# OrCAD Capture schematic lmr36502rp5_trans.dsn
size B; title: LMR36502RP5 Steady State Schematic; rev: A; note: <Doc>
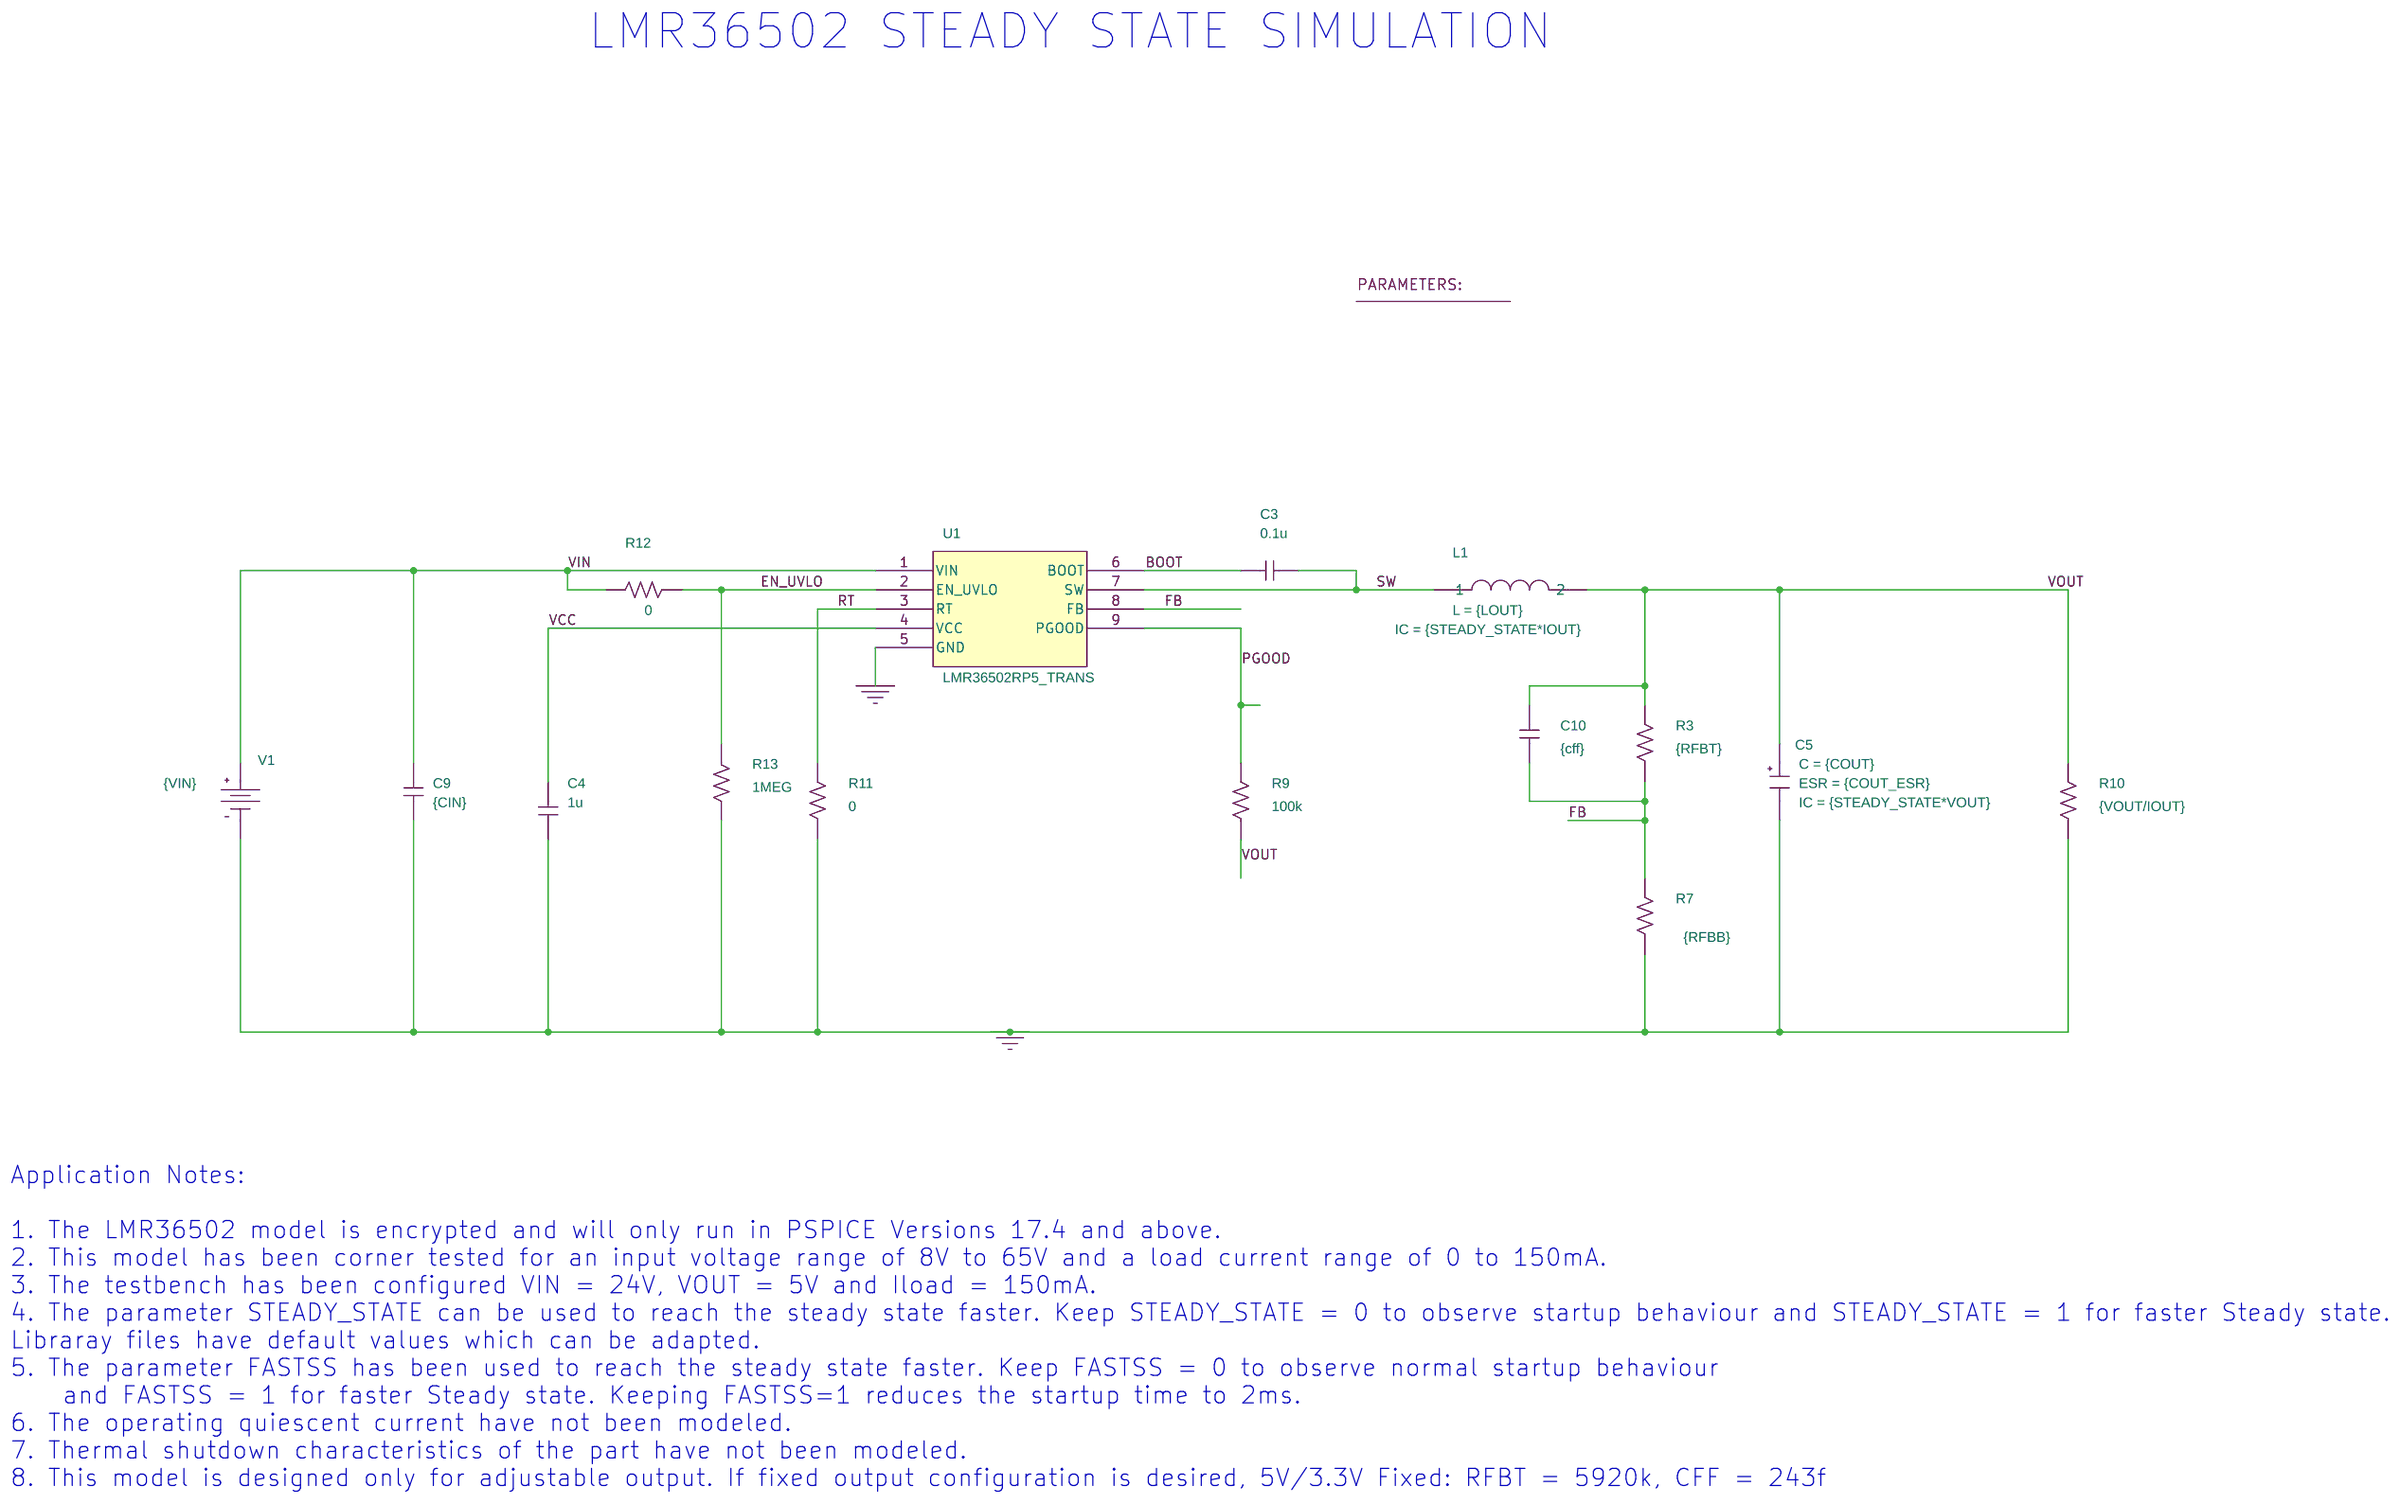
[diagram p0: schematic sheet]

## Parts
4  PARAM
C3  0.1u  [CK05]
C4  1u  [RAD/CK05]
C5  CESR
C9  {CIN}  [RAD/CK05]
C10  {cff}  [CK05]
L1  LDCR
R3  {RFBT}  [AX/RC05]
R7  {RFBB}  [AX/RC05]
R9  100k  [RC05]
R10  {VOUT/IOUT}  [AX/RC05]
R11  0  [AX/RC05]
R12  0  [AX/RC05]
R13  1MEG  [AX/RC05]
U1  LMR36502RP5_TRANS
V1  VDC

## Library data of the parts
4 = PARAM: CFF: 1f; CIN: 2.2u; COUT: 10u; COUT_ESR: 3m; FASTSS: 1; FSW: 2200; IOUT: .150; LOUT: 47u; RFBB: {{RFBT}/{VOUT-.9999}}; RFBT: 100k; STEADY_STATE: 1; TR_VIN: 100n; VIN: 24; VOUT: 5
C3 C10 = C: IC: 5
C4 = C: IC: {STEADY_STATE*5}
C5 = CESR_0: C: {COUT}; ESR: {COUT_ESR}; IC: {STEADY_STATE*VOUT}; PSpiceTemplate: X^@REFDES %IN %OUT @MODEL PARAMS:  ?C|C=@C||C=100u|  ?ESR|ESR=@ESR||ESR=0.01| ?X|X=@X||X=2|  ?IC|IC=@IC||IC=2|; X: 1
C9 = C
L1 = LDCR: DCR: 20m; IC: {STEADY_STATE*IOUT}; L: {LOUT}; PSpiceTemplate: X^@REFDES %1 %2 @MODEL PARAMS: ?L|L=@L||L=10U| ?DCR|DCR=@DCR||DCR=20M| ?IC|IC=@IC||IC=0|
R3 R7 R9-R13 = R
U1 = LMR36502RP5_TRANS
V1 = VDC: DC: {VIN}

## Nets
VCC: C4.1 U1.4(VCC)
VIN: C9.2 R12.2 U1.1(VIN) V1.0(+)
0: C4.2 C5.2(OUT) C9.1 R7.1 R10.1 R11.1 R13.2 U1.5(GND) V1.1(-)
BOOT: C3.1 U1.6(BOOT)
EN_UVLO: R12.1 R13.1 U1.2(EN_UVLO)
FB: C10.1 R3.1 R7.2 U1.8(FB)
PGOOD: R9.2 U1.9(PGOOD)
RT: R11.2 U1.3(RT)
SW: C3.2 L1.1 U1.7(SW)
VOUT: C5.1(IN) C10.2 L1.2 R3.2 R9.1 R10.2

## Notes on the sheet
- LMR36502 STEADY STATE SIMULATION
- Application Notes:
  1. The LMR36502 model is encrypted and will only run in PSPICE Versions 17.4 and above.
  2. This model has been corner tested for an input voltage range of 8V to 65V and a load current range of 0 to 150mA.
  3. The testbench has been configured VIN = 24V, VOUT = 5V and Iload = 150mA.
  4. The parameter STEADY_STATE can be used to reach the steady state faster. Keep STEADY_STATE = 0 to observe startup behaviour and STEADY_STATE = 1 for faster Steady state.
  Libraray files have default values which can be adapted.
  5. The parameter FASTSS has been used to reach the steady state faster. Keep FASTSS = 0 to observe normal startup behaviour
      and FASTSS = 1 for faster Steady state. Keeping FASTSS=1 reduces the startup time to 2ms.
  6. The operating quiescent current have not been modeled.
  7. Thermal shutdown characteristics of the part have not been modeled.
  8. This model is designed only for adjustable output. If fixed output configuration is desired, 5V/3.3V Fixed: RFBT = 5920k, CFF = 243f
